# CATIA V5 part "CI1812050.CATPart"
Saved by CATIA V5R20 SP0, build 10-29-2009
Part number: CI1812050
Bounding box of the stored display mesh (mm): x -12 to 12, y -9.866 to 68, z -15.524 to 13.481
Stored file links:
  C:\Users\Raffaele\Desktop\3D X SITO CF\BOLEX\19-INCLINED ASSEMBLY REF_CI\CI1812050.CATPart

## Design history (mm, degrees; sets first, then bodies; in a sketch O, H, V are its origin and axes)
Set1
  DatumSurface1 to DatumSurface16 "MANIFOLD_SOLID_BREP #377"
  DatumSurface17 to DatumSurface39 "MANIFOLD_SOLID_BREP #1094"
Body1 (main body)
